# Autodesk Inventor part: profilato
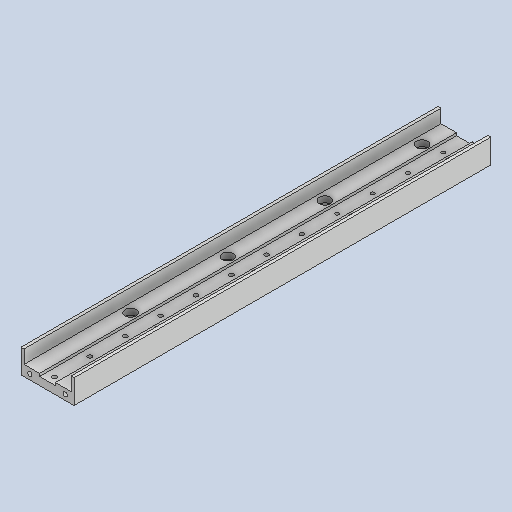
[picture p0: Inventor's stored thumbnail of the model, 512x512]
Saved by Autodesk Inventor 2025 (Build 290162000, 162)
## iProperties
Created: 2025-11
Part Number: profilato
Material: Generico
Document SubType Name: Modeling
Designer: Ryzen5700u
Density: 1 g/cm^3
Appearance: Default
Author: Ryzen5700u
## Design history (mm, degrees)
feature "Solido1"
node "Solido2"
